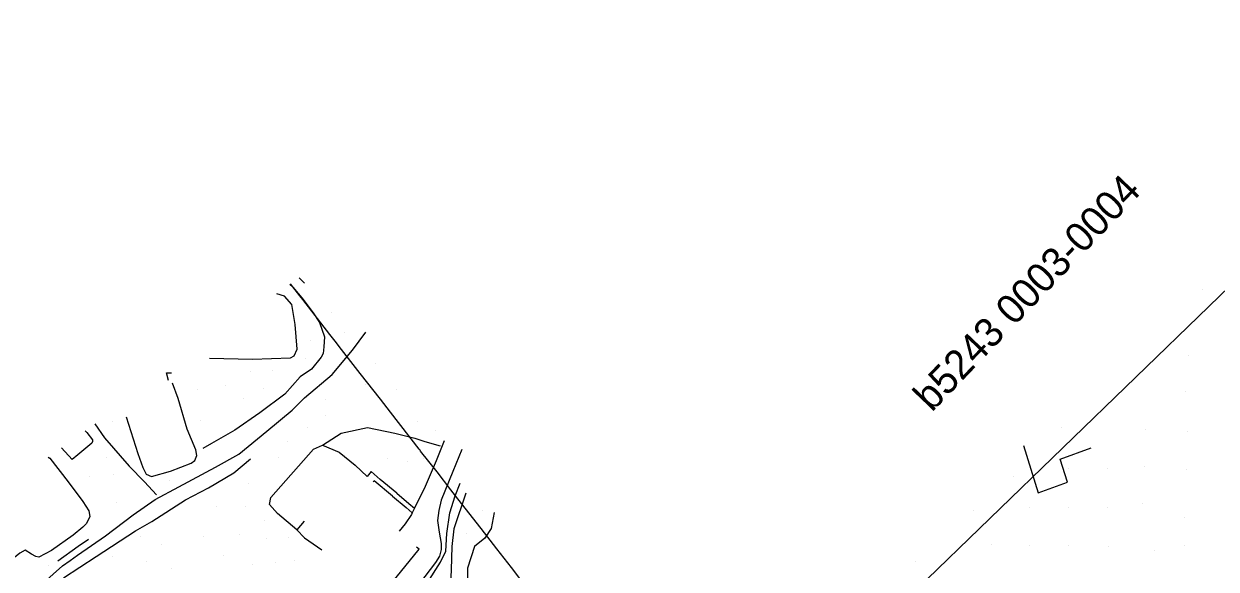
# Model space of a CAD drawing. Extents: x 1497074 to 1501343, y 481943 to 486114.
# Drawn here: x 1497425 to 1498040, y 484491 to 484772 of the extents above; entities that cross this region are included whole.
import ezdxf

# ---------------------------------------------------------------- set-up
doc = ezdxf.new("R2010")
doc.units = 0
for name, color, linetype in [('PH Exist DTM Boundary', 7, 'Continuous'), ('PH Exist DTM Boundary Text', 7, 'Continuous'), ('PH Exist DTM Breakline', 7, 'Continuous'), ('PH Exist DTM Point', 7, 'Continuous')]:
    doc.layers.add(name, color=color, linetype=linetype)

msp = doc.modelspace()

# ---------------------------------------------------------------- linework, layer by layer
at = {"layer": 'PH Exist DTM Boundary'}
msp.add_lwpolyline([(1497810.36, 484407.45), (1498181.14, 484070.49), (1498560.82, 484438.23), (1498186.43, 484771.69)], close=True, dxfattribs=at)
msp.add_lwpolyline([(1497682.07, 484484.47), (1497676.61, 484491.49), (1497669.09, 484501.14), (1497661.03, 484511.49), (1497649.09, 484526.82), (1497645.45, 484531.49), (1497638.29, 484540.69), (1497629.87, 484551.49), (1497629.53, 484551.93), (1497629.09, 484552.5), (1497614.3, 484571.49), (1497609.09, 484578.17), (1497598.72, 484591.49), (1497589.09, 484603.85), (1497585.75, 484608.15), (1497583.14, 484611.49), (1497569.09, 484629.53), (1497567.56, 484631.49), (1497562.81, 484637.59)], dxfattribs=at)
at = {"layer": 'PH Exist DTM Breakline'}
for points in [[(1497567.24, 484640.76), (1497569.95, 484637.98)], [(1497562.39, 484637.3), (1497564.07, 484635.96), (1497568.56, 484630.44), (1497574.45, 484622.67), (1497577.76, 484617.78), (1497580.31, 484610.41), (1497580.06, 484605.27), (1497579.6, 484601.85), (1497578.68, 484599.88), (1497573.59, 484593.62), (1497567.85, 484589.68), (1497559.88, 484580.88), (1497546.95, 484571.23), (1497534.17, 484562.25), (1497522.05, 484555.4), (1497517.67, 484552.85)], [(1497521.12, 484599.35), (1497543.29, 484598.92), (1497562.72, 484599.58), (1497564.77, 484600.58), (1497566.24, 484604.01), (1497565.23, 484616.69), (1497563.52, 484627.01), (1497559.79, 484631.33), (1497555.73, 484632.53)], [(1497380.31, 484444.03), (1497407.46, 484462.86), (1497432.52, 484480.83), (1497445.3, 484492.35), (1497449.21, 484495.11), (1497452.97, 484497.84), (1497467.42, 484507.84), (1497481.71, 484518.61), (1497492.98, 484526.47), (1497505.2, 484533.04), (1497524.07, 484543.21), (1497536.14, 484549.91), (1497550.63, 484561.75), (1497563.67, 484572.64), (1497570.03, 484578.99), (1497584.26, 484591.02), (1497594.69, 484603.43), (1497601.55, 484612.82)], [(1497499.97, 484587.9), (1497498.88, 484591.78), (1497501.49, 484591.78)], [(1497478.13, 484569.14), (1497484.2, 484550.23), (1497486.66, 484542.93), (1497488.47, 484539.61), (1497491.16, 484538.34), (1497500.99, 484541.1), (1497511.57, 484545.19), (1497513.42, 484546.55), (1497514.62, 484549.12), (1497513.94, 484552.12), (1497509.59, 484562.81), (1497504.98, 484578.59), (1497501.95, 484586.41)], [(1497457.08, 484561.94), (1497457.94, 484560.98), (1497460.78, 484557.29), (1497460.85, 484556.47), (1497460.43, 484555.62), (1497453.22, 484549.49), (1497450.37, 484547.14)], [(1497461.99, 484565.46), (1497466.92, 484558.35), (1497479.65, 484543.61), (1497487.6, 484535.53), (1497493.69, 484528.96)], [(1497579.35, 484554.44), (1497588.92, 484560.73), (1497602.45, 484563.56), (1497616.51, 484560.66), (1497626.79, 484558.18), (1497632.06, 484556.49)], [(1497566.13, 484510.85), (1497556.16, 484519.37), (1497551.99, 484523.98), (1497552.6, 484527.58), (1497574.57, 484552.39), (1497579.35, 484554.44), (1497587.88, 484550.93), (1497596.13, 484544.26), (1497602.39, 484538.45)], [(1497642.05, 484556.74), (1497637.82, 484546.38), (1497631.59, 484532.06), (1497627.46, 484523.6), (1497626.69, 484522.12), (1497625.5, 484519.68), (1497625.12, 484518.71), (1497621.95, 484513.97), (1497618.73, 484510.2)], [(1497632.06, 484556.49), (1497639.84, 484554.12)], [(1497940.42, 484554.26), (1497948.05, 484530.03), (1497963.22, 484535.46), (1497959.36, 484547.26), (1497975.34, 484553.09)], [(1497438, 484548.3), (1497438.75, 484547.82), (1497448.29, 484535.66), (1497455.84, 484525.45), (1497458.93, 484520.6), (1497459.34, 484517.68), (1497458.41, 484515.46), (1497457.51, 484514.05), (1497455.73, 484512.21), (1497450.73, 484508.04), (1497439.58, 484500.2), (1497433.19, 484496.82), (1497431.49, 484497.08), (1497429.37, 484498.31), (1497426.06, 484500.42), (1497423.32, 484498.86), (1497415.42, 484492.49)], [(1497450.37, 484547.14), (1497444.86, 484553.2)], [(1497651.15, 484552.35), (1497646.47, 484540.98), (1497640.51, 484526.24), (1497639.29, 484520.89), (1497638.6, 484515.68), (1497639.39, 484509.65), (1497640.39, 484503.87), (1497640.45, 484500.76), (1497639.66, 484497.24), (1497637.51, 484493.96), (1497629.34, 484483.19), (1497619.19, 484469.89), (1497612.95, 484461.53), (1497611.18, 484460.73)], [(1497445.75, 484486.2), (1497462.72, 484497.12), (1497482.97, 484510.34), (1497491.3, 484515.22), (1497508.62, 484526.4), (1497520.62, 484532.57), (1497533.54, 484540.25), (1497542.23, 484547.4)], [(1497617.56, 484529.8), (1497609.01, 484536.89), (1497604.28, 484540.88), (1497602.39, 484538.45)], [(1497615.36, 484528.27), (1497605.91, 484536.2), (1497605.32, 484535.62)], [(1497615.76, 484461.47), (1497626.15, 484473.91), (1497633.2, 484483.4), (1497640.11, 484494.23), (1497642.92, 484499.91), (1497643.32, 484508.97), (1497644.82, 484519.64), (1497647.73, 484528.36), (1497650.15, 484534.97)], [(1497617.56, 484529.8), (1497623.84, 484524.5), (1497626.69, 484522.12)], [(1497653.17, 484529.73), (1497646.96, 484511.32), (1497645.93, 484502.23), (1497645.64, 484490.19), (1497644.86, 484475.88), (1497643.56, 484463.04), (1497642.29, 484442.89), (1497641.83, 484432.67)], [(1497615.36, 484528.27), (1497622.39, 484522.36), (1497625.5, 484519.68)], [(1497667.69, 484519.75), (1497666.15, 484511.49), (1497662.96, 484506.58), (1497657.67, 484502.36), (1497654, 484491.1), (1497654.18, 484478.52), (1497657.33, 484468.16), (1497661.89, 484459.46), (1497666.01, 484454.99), (1497669.13, 484454.98), (1497681.13, 484457.79), (1497687.2, 484458.88)], [(1497569.78, 484515.31), (1497566.13, 484510.85), (1497569.93, 484506.74), (1497579.03, 484500.58)], [(1497442.91, 484494.93), (1497453.47, 484502.38), (1497458.75, 484506.05)], [(1497612.79, 484480.78), (1497629.08, 484500.83), (1497627.74, 484501.9)]]:
    msp.add_lwpolyline(points, dxfattribs=at)
at = {"layer": 'PH Exist DTM Point'}
for p, q in [((1498032.64, 484634.5), (1498032.64, 484634.5)), ((1497584.1, 484622.9), (1497584.1, 484622.9)), ((1497590.87, 484612.35), (1497590.87, 484612.35)), ((1497573.02, 484608.59), (1497573.02, 484608.59)), ((1497570.53, 484599.1), (1497570.53, 484599.1)), ((1498025.47, 484600.83), (1498025.47, 484600.83)), ((1497542.03, 484592.3), (1497542.03, 484592.3)), ((1497553.62, 484592.9), (1497553.62, 484592.9)), ((1497606.4, 484596.66), (1497606.4, 484596.66)), ((1497529.1, 484585.13), (1497529.1, 484585.13)), ((1497601.36, 484585.92), (1497601.36, 484585.92)), ((1497514.71, 484582.96), (1497514.71, 484582.96)), ((1497538.5, 484578.52), (1497538.5, 484578.52)), ((1497549.05, 484583.7), (1497549.05, 484583.7)), ((1497617.62, 484583.26), (1497617.62, 484583.26)), ((1498023.94, 484582.29), (1498023.94, 484582.29)), ((1497581, 484578.21), (1497581, 484578.21)), ((1497610.02, 484577.17), (1497610.02, 484577.17)), ((1497471.04, 484566.82), (1497471.04, 484566.82)), ((1497516.49, 484567.41), (1497516.49, 484567.41)), ((1497580.83, 484569.66), (1497580.83, 484569.66)), ((1497628.25, 484566.66), (1497628.25, 484566.66)), ((1497571.62, 484563.59), (1497571.62, 484563.59)), ((1497637.49, 484562.3), (1497637.49, 484562.3)), ((1497960.33, 484563.53), (1497960.33, 484563.53)), ((1498003.61, 484562.6), (1498003.61, 484562.6)), ((1498024.84, 484561.44), (1498024.84, 484561.44)), ((1497561.01, 484556.5), (1497561.01, 484556.5)), ((1497468.12, 484548.01), (1497468.12, 484548.01)), ((1497556.49, 484548.25), (1497556.49, 484548.25)), ((1497612.66, 484547.82), (1497612.66, 484547.82)), ((1497631.47, 484547.84), (1497631.47, 484547.84)), ((1497623.25, 484546.34), (1497623.25, 484546.34)), ((1497963.61, 484542.6), (1497963.61, 484542.6)), ((1497983.73, 484542.49), (1497983.73, 484542.49)), ((1498002.63, 484543.54), (1498002.63, 484543.54)), ((1498024.47, 484541.88), (1498024.47, 484541.88)), ((1497459.47, 484538.15), (1497459.47, 484538.15)), ((1497471.76, 484539.21), (1497471.76, 484539.21)), ((1497500.28, 484536.21), (1497500.28, 484536.21)), ((1497935.18, 484538.22), (1497935.18, 484538.22)), ((1497541.2, 484534.84), (1497541.2, 484534.84)), ((1497472.93, 484525.13), (1497472.93, 484525.13)), ((1497524.83, 484523.08), (1497524.83, 484523.08)), ((1497539.48, 484522.98), (1497539.48, 484522.98)), ((1498001.65, 484524.47), (1498001.65, 484524.47)), ((1497661.67, 484520.69), (1497661.67, 484520.69)), ((1497914.89, 484520.9), (1497914.89, 484520.9)), ((1497943.63, 484522.58), (1497943.63, 484522.58)), ((1497963.61, 484522.6), (1497963.61, 484522.6)), ((1497983.61, 484522.6), (1497983.61, 484522.6)), ((1498023.56, 484517.16), (1498023.56, 484517.16)), ((1497549.53, 484515.69), (1497549.53, 484515.69)), ((1497485.71, 484507.29), (1497485.71, 484507.29)), ((1497518.18, 484507.56), (1497518.18, 484507.56)), ((1497536.72, 484508.58), (1497536.72, 484508.58)), ((1497550.37, 484506.23), (1497550.37, 484506.23)), ((1497561.78, 484506.87), (1497561.78, 484506.87)), ((1497653.53, 484508.88), (1497653.53, 484508.88)), ((1497496.24, 484503.08), (1497496.24, 484503.08)), ((1497924.1, 484503.12), (1497924.1, 484503.12)), ((1497943.61, 484502.6), (1497943.61, 484502.6)), ((1497963.61, 484502.6), (1497963.61, 484502.6)), ((1497984.04, 484502.2), (1497984.04, 484502.2)), ((1498007.91, 484500.29), (1498007.91, 484500.29)), ((1498023.61, 484502.6), (1498023.61, 484502.6)), ((1497438.2, 484492.64), (1497438.2, 484492.64)), ((1497471.19, 484496.96), (1497471.19, 484496.96)), ((1497488.7, 484494.78), (1497488.7, 484494.78)), ((1497528.51, 484497.52), (1497528.51, 484497.52)), ((1497543.34, 484492.86), (1497543.34, 484492.86)), ((1497555.26, 484493.98), (1497555.26, 484493.98)), ((1497565.06, 484494.9), (1497565.06, 484494.9)), ((1497884.66, 484494.62), (1497884.66, 484494.62)), ((1497501.42, 484490.72), (1497501.42, 484490.72))]:
    msp.add_line(p, q, dxfattribs=at)

# ---------------------------------------------------------------- texts
at = {"layer": 'PH Exist DTM Boundary Text'}
msp.add_text('b5243 0003-0004', height=15, rotation=46.33816, dxfattribs=at).set_placement((1497893.26, 484571.21))

doc.saveas('drawing.dxf')
